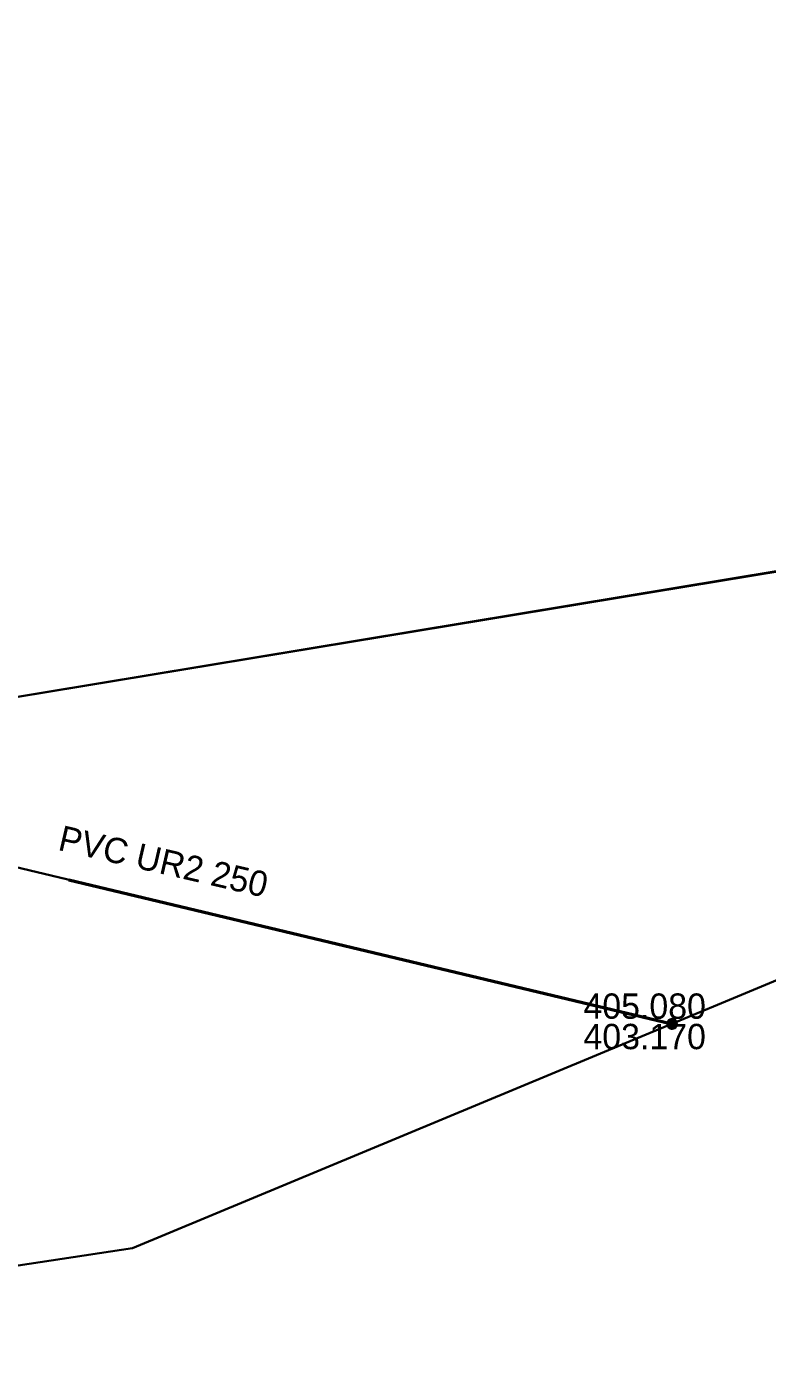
# Model space of a CAD drawing. Extents: x -873619 to -867639, y -1015082 to -1012326.
# Drawn here: x -868048.3 to -868016.1, y -1012871.4 to -1012813.6 of the extents above; entities that cross this region are included whole.
import ezdxf

# ---------------------------------------------------------------- set-up
doc = ezdxf.new("R2010")
doc.units = 0
doc.header["$LTSCALE"] = 0.44
for name, color, linetype, lineweight in [('1', 7, 'Continuous', 13), ('21', 7, 'Continuous', 35), ('26', 7, 'Continuous', 53), ('32', 7, 'Continuous', 13)]:
    doc.layers.add(name, color=color, linetype=linetype, lineweight=lineweight)

msp = doc.modelspace()

# ---------------------------------------------------------------- linework, layer by layer
at = {"layer": '1', "lineweight": 35}
for points in [[(-867974.611, -1012725.697), (-867976.949, -1012730.385), (-867980.624, -1012763.205), (-867983.112, -1012775.195), (-867978.719, -1012795.525), (-867979.823, -1012805.464), (-867997.768, -1012829.005), (-868011.042, -1012836.499), (-868058.95, -1012844.4), (-868077.43, -1012833.46), (-868085.171, -1012827.86)], [(-867997.768, -1012829.005), (-868011.041, -1012836.459), (-868058.95, -1012844.4)]]:
    msp.add_lwpolyline(points, dxfattribs=at)
at = {"layer": '21'}
for points in [[(-868376.717, -1012555.154), (-868316.566, -1012631.217), (-868240.045, -1012726.354), (-868207.711, -1012767.909), (-868167.337, -1012819.086), (-868122.692, -1012851.556), (-868075.313, -1012871.422), (-868043.707, -1012866.643), (-868020.287, -1012856.898)], [(-868134.19, -1012752.63), (-868112.27, -1012769.62), (-868107.42, -1012773.25), (-868101.75, -1012777.58), (-868093.15, -1012793.25), (-868087.37, -1012839.18), (-868062.459, -1012846.83), (-868020.28, -1012856.9)], [(-868020.287, -1012856.898), (-867997.903, -1012847.584), (-867988.318, -1012833.474), (-867978.718, -1012822.899), (-867965.69, -1012798.22), (-867965.665, -1012798.299)]]:
    msp.add_lwpolyline(points, dxfattribs=at)
at = {"layer": '26'}
msp.add_lwpolyline([(-868046.475, -1012850.646), (-868020.287, -1012856.898), (-868020.28, -1012856.9)], dxfattribs=at)
at = {"layer": '32'}
for points in [[(-868020.049, -1012856.899), (-868020.056, -1012856.847), (-868020.073, -1012856.797), (-868020.102, -1012856.753), (-868020.139, -1012856.716), (-868020.184, -1012856.689), (-868020.233, -1012856.672), (-868020.287, -1012856.668), (-868020.338, -1012856.675), (-868020.387, -1012856.694), (-868020.431, -1012856.723), (-868020.467, -1012856.762), (-868020.493, -1012856.807), (-868020.509, -1012856.858), (-868020.512, -1012856.91), (-868020.504, -1012856.962), (-868020.483, -1012857.011), (-868020.453, -1012857.054), (-868020.414, -1012857.088), (-868020.368, -1012857.114), (-868020.316, -1012857.128), (-868020.264, -1012857.13), (-868020.213, -1012857.12), (-868020.164, -1012857.099), (-868020.122, -1012857.068), (-868020.088, -1012857.027), (-868020.064, -1012856.981), (-868020.051, -1012856.93)], [(-868020.08, -1012856.899), (-868020.086, -1012856.85), (-868020.103, -1012856.804), (-868020.13, -1012856.764), (-868020.168, -1012856.732), (-868020.212, -1012856.71), (-868020.26, -1012856.699), (-868020.309, -1012856.699), (-868020.355, -1012856.712), (-868020.399, -1012856.736), (-868020.434, -1012856.769), (-868020.462, -1012856.81), (-868020.478, -1012856.857), (-868020.482, -1012856.906), (-868020.475, -1012856.954), (-868020.456, -1012856.999), (-868020.426, -1012857.039), (-868020.387, -1012857.07), (-868020.343, -1012857.09), (-868020.296, -1012857.1), (-868020.247, -1012857.098), (-868020.2, -1012857.083), (-868020.157, -1012857.058), (-868020.122, -1012857.024), (-868020.097, -1012856.982), (-868020.083, -1012856.935)], [(-868020.11, -1012856.899), (-868020.115, -1012856.854), (-868020.132, -1012856.812), (-868020.161, -1012856.777), (-868020.196, -1012856.75), (-868020.239, -1012856.733), (-868020.284, -1012856.728), (-868020.328, -1012856.734), (-868020.37, -1012856.753), (-868020.404, -1012856.781), (-868020.431, -1012856.818), (-868020.448, -1012856.86), (-868020.451, -1012856.905), (-868020.445, -1012856.95), (-868020.426, -1012856.991), (-868020.397, -1012857.025), (-868020.36, -1012857.051), (-868020.316, -1012857.067), (-868020.272, -1012857.07), (-868020.227, -1012857.062), (-868020.186, -1012857.042), (-868020.152, -1012857.013), (-868020.127, -1012856.975), (-868020.113, -1012856.932)], [(-868020.14, -1012856.899), (-868020.144, -1012856.858), (-868020.163, -1012856.821), (-868020.19, -1012856.79), (-868020.225, -1012856.769), (-868020.265, -1012856.758), (-868020.306, -1012856.76), (-868020.345, -1012856.773), (-868020.379, -1012856.797), (-868020.404, -1012856.829), (-868020.419, -1012856.867), (-868020.421, -1012856.908), (-868020.414, -1012856.948), (-868020.394, -1012856.984), (-868020.365, -1012857.013), (-868020.328, -1012857.032), (-868020.288, -1012857.04), (-868020.247, -1012857.036), (-868020.208, -1012857.021), (-868020.176, -1012856.995), (-868020.154, -1012856.961), (-868020.141, -1012856.922)], [(-868020.169, -1012856.899), (-868020.174, -1012856.863), (-868020.193, -1012856.831), (-868020.218, -1012856.806), (-868020.252, -1012856.791), (-868020.289, -1012856.788), (-868020.323, -1012856.796), (-868020.355, -1012856.816), (-868020.377, -1012856.844), (-868020.391, -1012856.878), (-868020.391, -1012856.915), (-868020.38, -1012856.95), (-868020.358, -1012856.979), (-868020.328, -1012857), (-868020.294, -1012857.01), (-868020.257, -1012857.008), (-868020.223, -1012856.994), (-868020.196, -1012856.971), (-868020.176, -1012856.939), (-868020.169, -1012856.904)], [(-868020.2, -1012856.899), (-868020.205, -1012856.868), (-868020.222, -1012856.842), (-868020.247, -1012856.825), (-868020.277, -1012856.818), (-868020.309, -1012856.822), (-868020.336, -1012856.839), (-868020.353, -1012856.863), (-868020.362, -1012856.894), (-868020.358, -1012856.924), (-868020.343, -1012856.952), (-868020.318, -1012856.971), (-868020.289, -1012856.98), (-868020.257, -1012856.977), (-868020.23, -1012856.963), (-868020.21, -1012856.939), (-868020.2, -1012856.91)], [(-868020.23, -1012856.899), (-868020.235, -1012856.875), (-868020.252, -1012856.857), (-868020.274, -1012856.848), (-868020.299, -1012856.851), (-868020.32, -1012856.865), (-868020.331, -1012856.887), (-868020.331, -1012856.912), (-868020.318, -1012856.933), (-868020.299, -1012856.947), (-868020.274, -1012856.95), (-868020.25, -1012856.941), (-868020.235, -1012856.923)], [(-868020.26, -1012856.899), (-868020.265, -1012856.884), (-868020.279, -1012856.878), (-868020.294, -1012856.882), (-868020.301, -1012856.896), (-868020.298, -1012856.911), (-868020.284, -1012856.92), (-868020.269, -1012856.917), (-868020.26, -1012856.905)]]:
    msp.add_lwpolyline(points, close=True, dxfattribs=at)

# ---------------------------------------------------------------- texts
at = {"layer": '1'}
msp.add_text('PVC UR2 250 ', height=1.1, rotation=347, dxfattribs=at).set_placement((-868046.987, -1012849.341))
for s, p in [('405.080 ', (-868024.131, -1012856.679)), ('403.170 ', (-868024.131, -1012857.999))]:
    msp.add_text(s, height=1.1, dxfattribs=at).set_placement(p)

doc.saveas('drawing.dxf')
